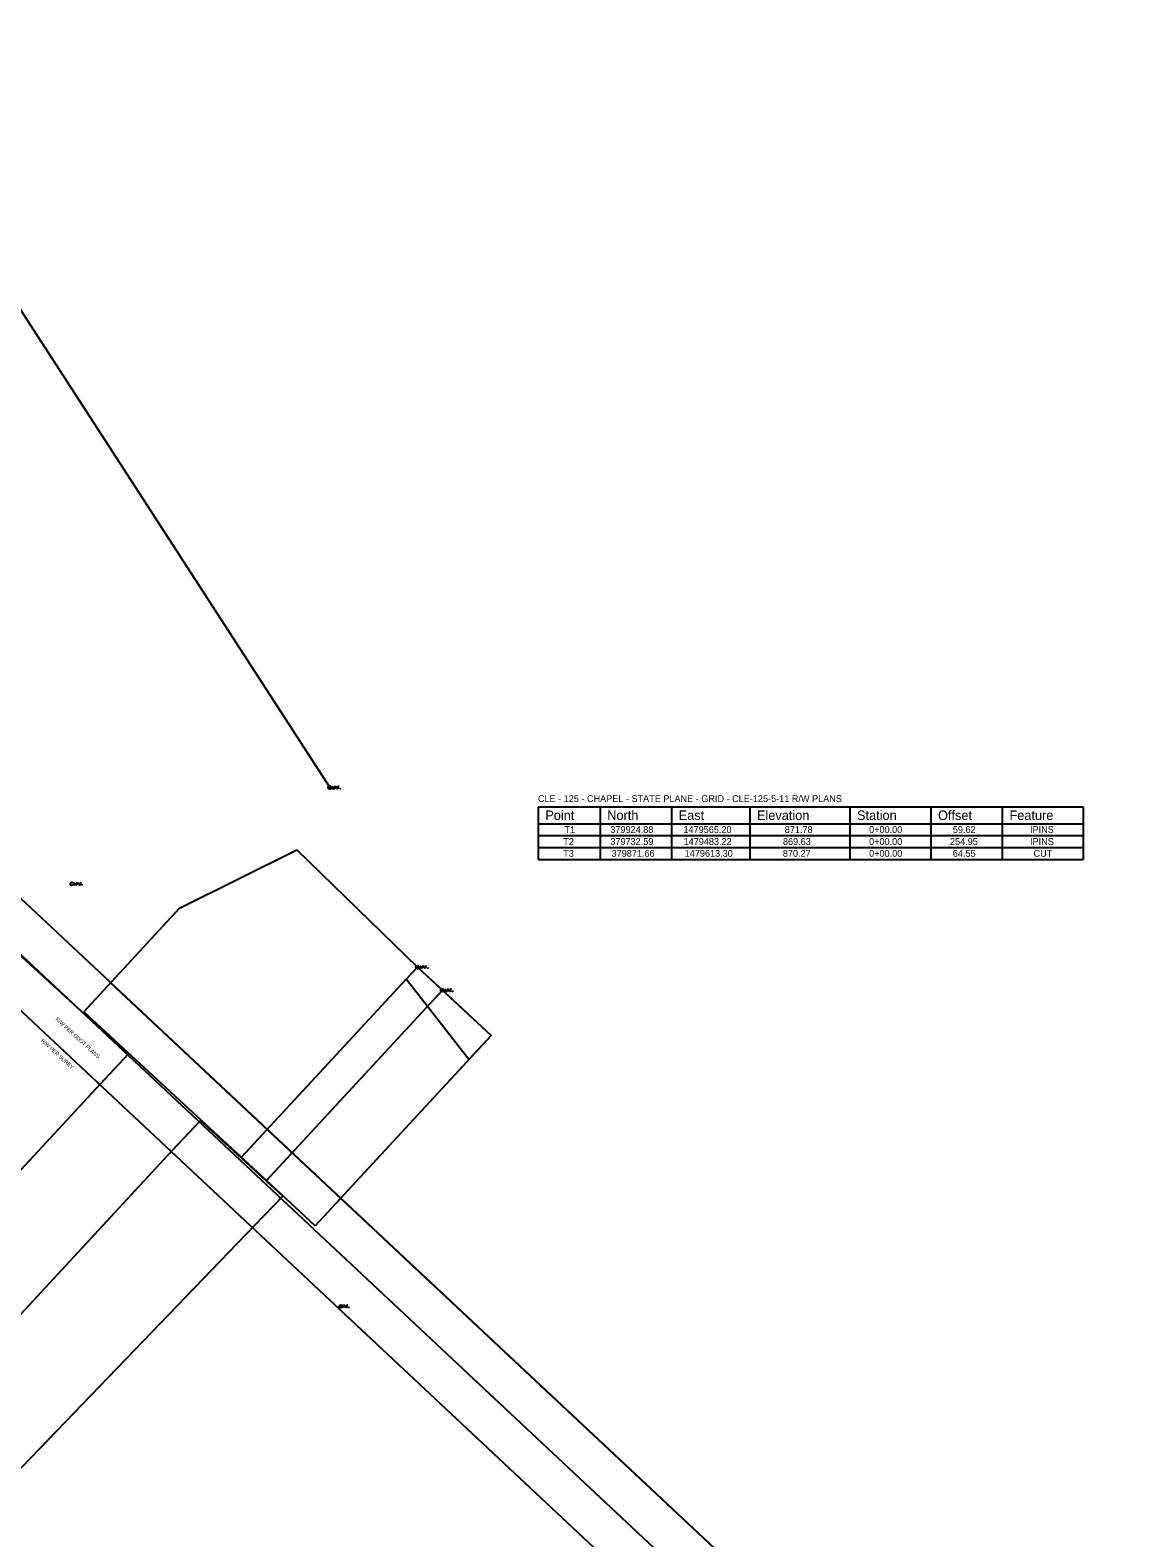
# Model space of a CAD drawing. Extents: x 1474121 to 1496246, y 364907 to 390007.
# Drawn here: x 1479633 to 1480434, y 379505 to 380613 of the extents above; entities that cross this region are included whole.
import ezdxf

# ---------------------------------------------------------------- set-up
doc = ezdxf.new("R2010")
doc.units = 0
for name, color, linetype in [('Default', 7, 'Continuous'), ('DV_X_Property_Line', 7, 'Continuous'), ('GE_X_CL_50', 7, 'Continuous'), ('RW_X_Esmt_SH', 7, 'Continuous'), ('SV_P_Mon_Cells_Set', 7, 'Continuous'), ('SV_X_Mon_Cells_Found', 7, 'Continuous'), ('SV_X_Text', 7, 'Continuous'), ('SV_X_Text_Elevation', 7, 'Continuous'), ('SV_X_Text_Name', 7, 'Continuous')]:
    doc.layers.add(name, color=color, linetype=linetype)

msp = doc.modelspace()

# ---------------------------------------------------------------- linework, layer by layer
at = {"layer": 'Default'}
for p, q in [((1480006.6, 380042), (1480407.1, 380042)), ((1480006.6, 380042), (1480006.6, 380003.5)), ((1480052.1, 380042), (1480052.1, 380003.5)), ((1480104.6, 380042), (1480104.6, 380003.5)), ((1480162.1, 380042), (1480162.1, 380003.5)), ((1480235.6, 380042), (1480235.6, 380003.5)), ((1480295.1, 380042), (1480295.1, 380003.5)), ((1480347.6, 380042), (1480347.6, 380003.5)), ((1480407.1, 380042), (1480407.1, 380003.5)), ((1480407.1, 380042), (1480407.1, 380003.5)), ((1480006.6, 380029.7), (1480407.1, 380029.7)), ((1480006.6, 380021), (1480407.1, 380021)), ((1480006.6, 380021), (1480407.1, 380021)), ((1480006.6, 380021), (1480407.1, 380021)), ((1480006.6, 380021), (1480407.1, 380021)), ((1480006.6, 380021), (1480407.1, 380021)), ((1480006.6, 380021), (1480407.1, 380021)), ((1480006.6, 380021), (1480407.1, 380021)), ((1480006.6, 380012.2), (1480407.1, 380012.2)), ((1480006.6, 380012.2), (1480407.1, 380012.2)), ((1480006.6, 380012.2), (1480407.1, 380012.2)), ((1480006.6, 380012.2), (1480407.1, 380012.2)), ((1480006.6, 380012.2), (1480407.1, 380012.2)), ((1480006.6, 380012.2), (1480407.1, 380012.2)), ((1480006.6, 380012.2), (1480407.1, 380012.2)), ((1480006.6, 380003.5), (1480407.1, 380003.5)), ((1480006.6, 380003.5), (1480407.1, 380003.5)), ((1480006.6, 380003.5), (1480407.1, 380003.5)), ((1480006.6, 380003.5), (1480407.1, 380003.5)), ((1480006.6, 380003.5), (1480407.1, 380003.5)), ((1480006.6, 380003.5), (1480407.1, 380003.5)), ((1480006.6, 380003.5), (1480407.1, 380003.5))]:
    msp.add_line(p, q, dxfattribs=at)
at = {"layer": 'DV_X_Property_Line'}
for p, q in [((1479516.3, 380577.1), (1479853.6, 380056.2)), ((1479743.3, 379967.7), (1479829.4, 380010.5)), ((1479829.4, 380010.5), (1479918, 379924.3)), ((1479672.8, 379891.5), (1479743.3, 379967.7)), ((1479621.7, 379937), (1479705.4, 379860.4)), ((1479918, 379924.3), (1479909.8, 379915.5)), ((1479909.8, 379915.5), (1479918, 379924.3)), ((1479936.3, 379907.4), (1479918, 379924.3)), ((1479918, 379924.3), (1479936.3, 379907.4)), ((1479918, 379924.3), (1479972.2, 379874.2)), ((1479909.8, 379915.5), (1479788.6, 379784.5)), ((1479955.7, 379856.4), (1479909.8, 379915.5)), ((1479807, 379767.5), (1479936.3, 379907.4)), ((1479936.3, 379907.4), (1479972.2, 379874.2)), ((1479807, 379767.5), (1479672.8, 379891.5)), ((1479972.2, 379874.2), (1479842.9, 379734.3)), ((1479972.2, 379874.2), (1479955.7, 379856.4)), ((1479705.4, 379860.4), (1479685, 379838.4)), ((1479685, 379838.4), (1479477.5, 379614.6)), ((1479738.1, 379789.8), (1479758.5, 379811.8)), ((1479758.5, 379811.8), (1479819.2, 379756.2)), ((1479528.5, 379563.5), (1479738.1, 379789.8)), ((1479788.6, 379784.5), (1479807, 379767.5)), ((1479842.9, 379734.3), (1479807, 379767.5)), ((1479819.2, 379756.2), (1479798.3, 379734.6)), ((1479798.3, 379734.6), (1479581.9, 379510))]:
    msp.add_line(p, q, dxfattribs=at)
at = {"layer": 'GE_X_CL_50'}
msp.add_line((1479566.7, 379989.5), (1480556, 379063.3), dxfattribs=at)
at = {"layer": 'RW_X_Esmt_SH'}
for p, q in [((1479546.2, 379967.6), (1480535.5, 379041.4)), ((1479692.5, 379912.8), (1480576.4, 379085.3))]:
    msp.add_line(p, q, dxfattribs=at)
msp.add_lwpolyline([(1477206.1, 382340.2), (1479587.4, 380011.2), (1480576.4, 379085.3), (1481364.4, 378357.4), (1481874.1, 377874.9), (1482608.9, 377164.9), (1482870.8, 376903.4), (1483684.1, 376107.4), (1484321.2, 375944.1)], dxfattribs=at)
at = {"layer": 'SV_P_Mon_Cells_Set'}
for points in [[(1479666.1, 379986.3), (1479666.4, 379986.3)], [(1479666.1, 379984.7), (1479666.4, 379984.7)], [(1479666.2, 379984.7), (1479666.2, 379986.3)], [(1479667.2, 379984.9), (1479667.3, 379984.9), (1479667.3, 379984.9), (1479667.3, 379984.9), (1479667.3, 379984.8), (1479667.3, 379984.8), (1479667.3, 379984.7), (1479667.2, 379984.7), (1479667.2, 379984.8), (1479667.1, 379984.8), (1479667.1, 379984.9), (1479667.2, 379984.9), (1479667.2, 379984.9)], [(1479667.8, 379984.7), (1479667.8, 379986.3), (1479668.3, 379986.3), (1479668.4, 379986.3), (1479668.5, 379986.3), (1479668.5, 379986.3), (1479668.5, 379986.2), (1479668.6, 379986.2), (1479668.6, 379986.1), (1479668.6, 379986), (1479668.6, 379985.9), (1479668.6, 379985.8), (1479668.6, 379985.7), (1479668.6, 379985.7), (1479668.5, 379985.6), (1479668.5, 379985.6), (1479668.4, 379985.6), (1479668.3, 379985.5), (1479667.8, 379985.5)], [(1479669.5, 379984.9), (1479669.5, 379984.9), (1479669.5, 379984.9), (1479669.6, 379984.9), (1479669.6, 379984.8), (1479669.5, 379984.8), (1479669.5, 379984.7), (1479669.5, 379984.7), (1479669.4, 379984.8), (1479669.4, 379984.8), (1479669.4, 379984.9), (1479669.4, 379984.9), (1479669.5, 379984.9)], [(1479670.8, 379986.2), (1479670.8, 379986.2), (1479670.8, 379986.3), (1479670.7, 379986.3), (1479670.5, 379986.3), (1479670.5, 379986.3), (1479670.4, 379986.3), (1479670.3, 379986.3), (1479670.2, 379986.2), (1479670.1, 379986.1), (1479670.1, 379986), (1479670.1, 379985.9), (1479670.1, 379985.8), (1479670.2, 379985.8), (1479670.8, 379985.4), (1479670.8, 379985.3), (1479670.9, 379985.3), (1479670.9, 379985.2), (1479670.9, 379985.1), (1479670.9, 379985), (1479670.9, 379985), (1479670.8, 379984.9), (1479670.8, 379984.9), (1479670.8, 379984.8), (1479670.8, 379984.8), (1479670.7, 379984.8), (1479670.7, 379984.8), (1479670.6, 379984.7), (1479670.5, 379984.7), (1479670.4, 379984.7), (1479670.3, 379984.8), (1479670.2, 379984.8), (1479670.1, 379984.9)], [(1479671.6, 379984.9), (1479671.7, 379984.9), (1479671.7, 379984.9), (1479671.8, 379984.9), (1479671.8, 379984.8), (1479671.7, 379984.8), (1479671.7, 379984.7), (1479671.6, 379984.7), (1479671.6, 379984.8), (1479671.6, 379984.8), (1479671.6, 379984.9), (1479671.6, 379984.9), (1479671.6, 379984.9)]]:
    msp.add_lwpolyline(points, dxfattribs=at)
msp.add_circle((1479664.1, 379985.5), 1.2, dxfattribs=at)
at = {"layer": 'SV_X_Mon_Cells_Found'}
for p, q in [((1479853.6, 380056.3), (1479853.6, 380055.4)), ((1479853.6, 380056.3), (1479853.6, 380055.4)), ((1479918, 379924.5), (1479918, 379923.6)), ((1479918, 379924.5), (1479918, 379923.6))]:
    msp.add_line(p, q, dxfattribs=at)
for points in [[(1479855.6, 380057), (1479856, 380057)], [(1479855.6, 380057), (1479856, 380057)], [(1479855.6, 380055.4), (1479856, 380055.4)], [(1479855.6, 380055.4), (1479856, 380055.4)], [(1479855.8, 380055.4), (1479855.8, 380057)], [(1479855.8, 380055.4), (1479855.8, 380057)], [(1479856.8, 380055.6), (1479856.8, 380055.6), (1479856.9, 380055.6), (1479856.9, 380055.5), (1479856.9, 380055.5), (1479856.9, 380055.4), (1479856.8, 380055.4), (1479856.8, 380055.4), (1479856.7, 380055.4), (1479856.7, 380055.5), (1479856.7, 380055.5), (1479856.7, 380055.6), (1479856.8, 380055.6)], [(1479856.8, 380055.6), (1479856.8, 380055.6), (1479856.9, 380055.6), (1479856.9, 380055.5), (1479856.9, 380055.5), (1479856.9, 380055.4), (1479856.8, 380055.4), (1479856.8, 380055.4), (1479856.7, 380055.4), (1479856.7, 380055.5), (1479856.7, 380055.5), (1479856.7, 380055.6), (1479856.8, 380055.6)], [(1479857.4, 380055.4), (1479857.4, 380057), (1479857.9, 380057), (1479858, 380057), (1479858, 380057), (1479858.1, 380056.9), (1479858.1, 380056.9), (1479858.1, 380056.8), (1479858.2, 380056.8), (1479858.2, 380056.7), (1479858.2, 380056.5), (1479858.2, 380056.5), (1479858.2, 380056.4), (1479858.1, 380056.3), (1479858.1, 380056.3), (1479858, 380056.2), (1479858, 380056.2), (1479857.9, 380056.2), (1479857.4, 380056.2)], [(1479857.4, 380055.4), (1479857.4, 380057), (1479857.9, 380057), (1479858, 380057), (1479858, 380057), (1479858.1, 380056.9), (1479858.1, 380056.9), (1479858.1, 380056.8), (1479858.2, 380056.8), (1479858.2, 380056.7), (1479858.2, 380056.5), (1479858.2, 380056.5), (1479858.2, 380056.4), (1479858.1, 380056.3), (1479858.1, 380056.3), (1479858, 380056.2), (1479858, 380056.2), (1479857.9, 380056.2), (1479857.4, 380056.2)], [(1479859, 380055.6), (1479859.1, 380055.6), (1479859.1, 380055.6), (1479859.1, 380055.5), (1479859.1, 380055.5), (1479859.1, 380055.4), (1479859.1, 380055.4), (1479859, 380055.4), (1479859, 380055.4), (1479858.9, 380055.5), (1479858.9, 380055.5), (1479859, 380055.6), (1479859, 380055.6)], [(1479859, 380055.6), (1479859.1, 380055.6), (1479859.1, 380055.6), (1479859.1, 380055.5), (1479859.1, 380055.5), (1479859.1, 380055.4), (1479859.1, 380055.4), (1479859, 380055.4), (1479859, 380055.4), (1479858.9, 380055.5), (1479858.9, 380055.5), (1479859, 380055.6), (1479859, 380055.6)], [(1479860.4, 380057), (1479859.6, 380057), (1479859.6, 380055.4)], [(1479860.4, 380057), (1479859.6, 380057), (1479859.6, 380055.4)], [(1479859.6, 380056.2), (1479860.2, 380056.2)], [(1479859.6, 380056.2), (1479860.2, 380056.2)], [(1479861.2, 380055.6), (1479861.2, 380055.6), (1479861.3, 380055.6), (1479861.3, 380055.5), (1479861.3, 380055.5), (1479861.3, 380055.4), (1479861.2, 380055.4), (1479861.2, 380055.4), (1479861.1, 380055.4), (1479861.1, 380055.5), (1479861.1, 380055.5), (1479861.1, 380055.6), (1479861.2, 380055.6)], [(1479861.2, 380055.6), (1479861.2, 380055.6), (1479861.3, 380055.6), (1479861.3, 380055.5), (1479861.3, 380055.5), (1479861.3, 380055.4), (1479861.2, 380055.4), (1479861.2, 380055.4), (1479861.1, 380055.4), (1479861.1, 380055.5), (1479861.1, 380055.5), (1479861.1, 380055.6), (1479861.2, 380055.6)], [(1479920, 379925.1), (1479920.3, 379925.1)], [(1479920, 379925.1), (1479920.3, 379925.1)], [(1479920, 379923.5), (1479920.3, 379923.5)], [(1479920, 379923.5), (1479920.3, 379923.5)], [(1479920.2, 379923.5), (1479920.2, 379925.1)], [(1479920.2, 379923.5), (1479920.2, 379925.1)], [(1479921.1, 379923.8), (1479921.2, 379923.8), (1479921.2, 379923.7), (1479921.2, 379923.7), (1479921.2, 379923.6), (1479921.2, 379923.6), (1479921.2, 379923.5), (1479921.1, 379923.5), (1479921.1, 379923.6), (1479921.1, 379923.6), (1479921.1, 379923.7), (1479921.1, 379923.7), (1479921.1, 379923.8)], [(1479921.1, 379923.8), (1479921.2, 379923.8), (1479921.2, 379923.7), (1479921.2, 379923.7), (1479921.2, 379923.6), (1479921.2, 379923.6), (1479921.2, 379923.5), (1479921.1, 379923.5), (1479921.1, 379923.6), (1479921.1, 379923.6), (1479921.1, 379923.7), (1479921.1, 379923.7), (1479921.1, 379923.8)], [(1479921.7, 379923.5), (1479921.7, 379925.1), (1479922.3, 379925.1), (1479922.3, 379925.1), (1479922.4, 379925.1), (1479922.4, 379925.1), (1479922.5, 379925.1), (1479922.5, 379925), (1479922.5, 379924.9), (1479922.6, 379924.8), (1479922.6, 379924.7), (1479922.5, 379924.6), (1479922.5, 379924.6), (1479922.5, 379924.5), (1479922.4, 379924.4), (1479922.4, 379924.4), (1479922.3, 379924.4), (1479922.3, 379924.4), (1479921.7, 379924.4)], [(1479921.7, 379923.5), (1479921.7, 379925.1), (1479922.3, 379925.1), (1479922.3, 379925.1), (1479922.4, 379925.1), (1479922.4, 379925.1), (1479922.5, 379925.1), (1479922.5, 379925), (1479922.5, 379924.9), (1479922.6, 379924.8), (1479922.6, 379924.7), (1479922.5, 379924.6), (1479922.5, 379924.6), (1479922.5, 379924.5), (1479922.4, 379924.4), (1479922.4, 379924.4), (1479922.3, 379924.4), (1479922.3, 379924.4), (1479921.7, 379924.4)], [(1479923.4, 379923.8), (1479923.4, 379923.8), (1479923.5, 379923.7), (1479923.5, 379923.7), (1479923.5, 379923.6), (1479923.5, 379923.6), (1479923.4, 379923.5), (1479923.4, 379923.5), (1479923.3, 379923.6), (1479923.3, 379923.6), (1479923.3, 379923.7), (1479923.3, 379923.7), (1479923.4, 379923.8)], [(1479923.4, 379923.8), (1479923.4, 379923.8), (1479923.5, 379923.7), (1479923.5, 379923.7), (1479923.5, 379923.6), (1479923.5, 379923.6), (1479923.4, 379923.5), (1479923.4, 379923.5), (1479923.3, 379923.6), (1479923.3, 379923.6), (1479923.3, 379923.7), (1479923.3, 379923.7), (1479923.4, 379923.8)], [(1479924.7, 379925.1), (1479924, 379925.1), (1479924, 379923.5)], [(1479924.7, 379925.1), (1479924, 379925.1), (1479924, 379923.5)], [(1479924, 379924.4), (1479924.5, 379924.4)], [(1479924, 379924.4), (1479924.5, 379924.4)], [(1479925.5, 379923.8), (1479925.6, 379923.8), (1479925.6, 379923.7), (1479925.6, 379923.7), (1479925.6, 379923.6), (1479925.6, 379923.6), (1479925.6, 379923.5), (1479925.5, 379923.5), (1479925.5, 379923.6), (1479925.5, 379923.6), (1479925.5, 379923.7), (1479925.5, 379923.7), (1479925.5, 379923.8)], [(1479925.5, 379923.8), (1479925.6, 379923.8), (1479925.6, 379923.7), (1479925.6, 379923.7), (1479925.6, 379923.6), (1479925.6, 379923.6), (1479925.6, 379923.5), (1479925.5, 379923.5), (1479925.5, 379923.6), (1479925.5, 379923.6), (1479925.5, 379923.7), (1479925.5, 379923.7), (1479925.5, 379923.8)], [(1479938.3, 379908.1), (1479938.6, 379908.1)], [(1479938.3, 379908.1), (1479938.6, 379908.1)], [(1479938.3, 379906.5), (1479938.6, 379906.5)], [(1479938.3, 379906.5), (1479938.6, 379906.5)], [(1479938.4, 379906.5), (1479938.4, 379908.1)], [(1479938.4, 379906.5), (1479938.4, 379908.1)], [(1479939.4, 379906.7), (1479939.4, 379906.7), (1479939.5, 379906.7), (1479939.5, 379906.6), (1479939.5, 379906.5), (1479939.5, 379906.5), (1479939.4, 379906.5), (1479939.4, 379906.5), (1479939.4, 379906.5), (1479939.3, 379906.5), (1479939.3, 379906.6), (1479939.4, 379906.7), (1479939.4, 379906.7)], [(1479939.4, 379906.7), (1479939.4, 379906.7), (1479939.5, 379906.7), (1479939.5, 379906.6), (1479939.5, 379906.5), (1479939.5, 379906.5), (1479939.4, 379906.5), (1479939.4, 379906.5), (1479939.4, 379906.5), (1479939.3, 379906.5), (1479939.3, 379906.6), (1479939.4, 379906.7), (1479939.4, 379906.7)], [(1479940, 379906.5), (1479940, 379908.1), (1479940.5, 379908.1), (1479940.6, 379908.1), (1479940.7, 379908), (1479940.7, 379908), (1479940.7, 379908), (1479940.8, 379907.9), (1479940.8, 379907.9), (1479940.8, 379907.8), (1479940.8, 379907.6), (1479940.8, 379907.6), (1479940.8, 379907.5), (1479940.7, 379907.4), (1479940.7, 379907.4), (1479940.7, 379907.3), (1479940.6, 379907.3), (1479940.5, 379907.3), (1479940, 379907.3)], [(1479940, 379906.5), (1479940, 379908.1), (1479940.5, 379908.1), (1479940.6, 379908.1), (1479940.7, 379908), (1479940.7, 379908), (1479940.7, 379908), (1479940.8, 379907.9), (1479940.8, 379907.9), (1479940.8, 379907.8), (1479940.8, 379907.6), (1479940.8, 379907.6), (1479940.8, 379907.5), (1479940.7, 379907.4), (1479940.7, 379907.4), (1479940.7, 379907.3), (1479940.6, 379907.3), (1479940.5, 379907.3), (1479940, 379907.3)], [(1479941.6, 379906.7), (1479941.7, 379906.7), (1479941.7, 379906.7), (1479941.8, 379906.6), (1479941.8, 379906.5), (1479941.7, 379906.5), (1479941.7, 379906.5), (1479941.6, 379906.5), (1479941.6, 379906.5), (1479941.6, 379906.5), (1479941.6, 379906.6), (1479941.6, 379906.7), (1479941.6, 379906.7)], [(1479941.6, 379906.7), (1479941.7, 379906.7), (1479941.7, 379906.7), (1479941.8, 379906.6), (1479941.8, 379906.5), (1479941.7, 379906.5), (1479941.7, 379906.5), (1479941.6, 379906.5), (1479941.6, 379906.5), (1479941.6, 379906.5), (1479941.6, 379906.6), (1479941.6, 379906.7), (1479941.6, 379906.7)], [(1479943, 379908.1), (1479942.2, 379908.1), (1479942.2, 379906.5)], [(1479943, 379908.1), (1479942.2, 379908.1), (1479942.2, 379906.5)], [(1479942.2, 379907.3), (1479942.8, 379907.3)], [(1479942.2, 379907.3), (1479942.8, 379907.3)], [(1479943.8, 379906.7), (1479943.8, 379906.7), (1479943.9, 379906.7), (1479943.9, 379906.6), (1479943.9, 379906.5), (1479943.9, 379906.5), (1479943.8, 379906.5), (1479943.8, 379906.5), (1479943.8, 379906.5), (1479943.7, 379906.5), (1479943.7, 379906.6), (1479943.8, 379906.7), (1479943.8, 379906.7)], [(1479943.8, 379906.7), (1479943.8, 379906.7), (1479943.9, 379906.7), (1479943.9, 379906.6), (1479943.9, 379906.5), (1479943.9, 379906.5), (1479943.8, 379906.5), (1479943.8, 379906.5), (1479943.8, 379906.5), (1479943.7, 379906.5), (1479943.7, 379906.6), (1479943.8, 379906.7), (1479943.8, 379906.7)], [(1479863.8, 379674.4), (1479863.8, 379676), (1479864.3, 379676), (1479864.4, 379676), (1479864.5, 379676), (1479864.5, 379676), (1479864.5, 379675.9), (1479864.6, 379675.9), (1479864.6, 379675.8), (1479864.6, 379675.7), (1479864.6, 379675.6), (1479864.6, 379675.5), (1479864.6, 379675.4), (1479864.5, 379675.3), (1479864.5, 379675.3), (1479864.5, 379675.3), (1479864.4, 379675.3), (1479864.3, 379675.2), (1479863.8, 379675.2)], [(1479863.8, 379674.4), (1479863.8, 379676), (1479864.3, 379676), (1479864.4, 379676), (1479864.5, 379676), (1479864.5, 379676), (1479864.5, 379675.9), (1479864.6, 379675.9), (1479864.6, 379675.8), (1479864.6, 379675.7), (1479864.6, 379675.6), (1479864.6, 379675.5), (1479864.6, 379675.4), (1479864.5, 379675.3), (1479864.5, 379675.3), (1479864.5, 379675.3), (1479864.4, 379675.3), (1479864.3, 379675.2), (1479863.8, 379675.2)], [(1479865.4, 379674.6), (1479865.5, 379674.6), (1479865.5, 379674.6), (1479865.6, 379674.6), (1479865.6, 379674.5), (1479865.5, 379674.5), (1479865.5, 379674.4), (1479865.4, 379674.4), (1479865.4, 379674.5), (1479865.4, 379674.5), (1479865.4, 379674.6), (1479865.4, 379674.6), (1479865.4, 379674.6)], [(1479865.4, 379674.6), (1479865.5, 379674.6), (1479865.5, 379674.6), (1479865.6, 379674.6), (1479865.6, 379674.5), (1479865.5, 379674.5), (1479865.5, 379674.4), (1479865.4, 379674.4), (1479865.4, 379674.5), (1479865.4, 379674.5), (1479865.4, 379674.6), (1479865.4, 379674.6), (1479865.4, 379674.6)], [(1479866.8, 379676), (1479866, 379676), (1479866, 379674.4)], [(1479866.8, 379676), (1479866, 379676), (1479866, 379674.4)], [(1479866, 379675.2), (1479866.6, 379675.2)], [(1479866, 379675.2), (1479866.6, 379675.2)], [(1479867.6, 379674.6), (1479867.6, 379674.6), (1479867.7, 379674.6), (1479867.7, 379674.6), (1479867.7, 379674.5), (1479867.7, 379674.5), (1479867.6, 379674.4), (1479867.6, 379674.4), (1479867.6, 379674.5), (1479867.5, 379674.5), (1479867.5, 379674.6), (1479867.6, 379674.6), (1479867.6, 379674.6)], [(1479867.6, 379674.6), (1479867.6, 379674.6), (1479867.7, 379674.6), (1479867.7, 379674.6), (1479867.7, 379674.5), (1479867.7, 379674.5), (1479867.6, 379674.4), (1479867.6, 379674.4), (1479867.6, 379674.5), (1479867.5, 379674.5), (1479867.5, 379674.6), (1479867.6, 379674.6), (1479867.6, 379674.6)]]:
    msp.add_lwpolyline(points, dxfattribs=at)
for centre, radius in [((1479853.6, 380056.2), 1.2), ((1479853.6, 380056.2), 1.2), ((1479853.6, 380056.8), 0.16), ((1479853.6, 380056.8), 0.16), ((1479918, 379924.3), 1.2), ((1479918, 379924.3), 1.2), ((1479918, 379925), 0.16), ((1479918, 379925), 0.16), ((1479936.2, 379907.3), 1.2), ((1479936.2, 379907.3), 1.2), ((1479861.8, 379675.2), 1.2), ((1479861.8, 379675.2), 1.2), ((1479861.8, 379675.2), 0.495), ((1479861.8, 379675.2), 0.495)]:
    msp.add_circle(centre, radius, dxfattribs=at)

# ---------------------------------------------------------------- texts
at = {"layer": 'Default'}
for s, height, p in [('Point', 7, (1480011.9, 380032.4)), ('North', 7, (1480057.4, 380032.4)), ('East', 7, (1480109.9, 380032.4)), ('Elevation', 7, (1480167.4, 380032.4)), ('Station', 7, (1480240.9, 380032.4)), ('Offset', 7, (1480300.4, 380032.4)), ('Feature', 7, (1480352.9, 380032.4)), ('T1', 5, (1480026, 380022.9)), ('379924.88', 5, (1480059.7, 380022.9)), ('1479565.20', 5, (1480113.4, 380022.9)), ('871.78', 5, (1480187.8, 380022.9)), ('0+00.00', 5, (1480249.8, 380022.9)), ('59.62', 5, (1480311.3, 380022.9)), ('IPINS', 5, (1480368, 380022.9)), ('T3', 5, (1480025.1, 380005.4)), ('T2', 5, (1480025.1, 380014.1)), ('379732.59', 5, (1480059.7, 380014.1)), ('379871.66', 5, (1480060.6, 380005.4)), ('1479483.22', 5, (1480113.5, 380014.1)), ('1479613.30', 5, (1480114.3, 380005.4)), ('870.27', 5, (1480186.4, 380005.4)), ('869.63', 5, (1480186.5, 380014.1)), ('0+00.00', 5, (1480249.8, 380014.1)), ('0+00.00', 5, (1480249.8, 380005.4)), ('254.95', 5, (1480309.2, 380014.1)), ('64.55', 5, (1480311.3, 380005.4)), ('IPINS', 5, (1480368, 380014.1)), ('CUT', 5, (1480370.6, 380005.4))]:
    msp.add_text(s, height=height, dxfattribs=at).set_placement(p)
at = {"layer": 'SV_X_Text'}
msp.add_text('CLE - 125 - CHAPEL - STATE PLANE - GRID - CLE-125-5-11 R/W PLANS', height=5, dxfattribs=at).set_placement((1480006.5, 380045.6))
for s, p in [('R/W PER ODOT PLANS', (1479651.8, 379885.7)), ('R/W PER SUREY', (1479641.1, 379870))]:
    msp.add_text(s, height=2.8, rotation=317.5331, dxfattribs=at).set_placement(p)
at = {"layer": 'SV_X_Text_Elevation'}
for s, p in [('866.88', (1479853.3, 380056.1)), ('865.96', (1479917.7, 379924.3)), ('865.56', (1479936, 379907.2)), ('865.44', (1479861.5, 379675.2))]:
    msp.add_text(s, height=0.06, dxfattribs=at).set_placement(p)
at = {"layer": 'SV_X_Text_Name'}
for s, p in [('FV253', (1479853.4, 380056.2)), ('FV200', (1479917.7, 379924.3)), ('FV201', (1479936, 379907.3)), ('FV257', (1479861.6, 379675.2))]:
    msp.add_text(s, height=0.06, dxfattribs=at).set_placement(p)

doc.saveas('drawing.dxf')
